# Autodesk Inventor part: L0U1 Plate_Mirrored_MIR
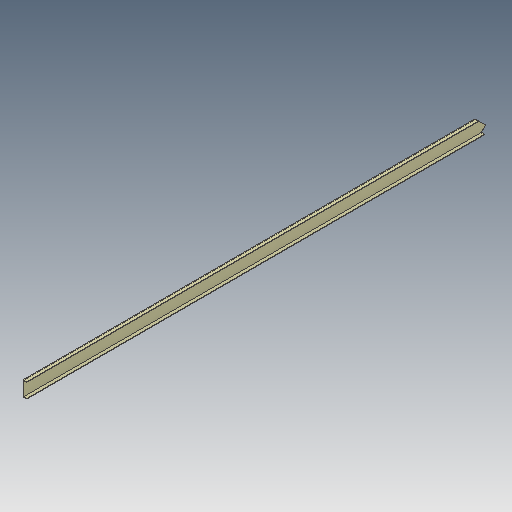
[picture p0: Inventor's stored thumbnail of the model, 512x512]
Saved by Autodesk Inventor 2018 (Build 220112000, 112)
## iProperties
Created: 2018-02
Part Number: L0U1 Plate_Mirrored_MIR
Material: Steel, Mild
Document SubType Name: Sheet Metal
Designer: STK
Density: 7.85 g/cm^3
Sheet Metal Rule: Default
Appearance: Semi-Polished
Mass: 625157 g
Surface Area: 128515 cm^2
Volume: 79637.8 cm^3
Author: STK
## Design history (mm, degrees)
derived "L0U1 Plate_Mirrored.ipt"
feature "Solid1::L0U1 Plate_Mirrored.ipt" dims "d0" = 10
tag "TaggingFeature1"
body "Solid1"
other parameters: "Thickness" = 3.048, "BendRadius" = 3.048 (= Thickness), "BendReliefWidth" = 3.048 (= Thickness), "BendReliefDepth" = 1.524 (= 0.5 x Thickness), "CornerReliefSize" = 12.192 (= 4 x Thickness), "SeamGap" = 0.00508, "MinimumRemnant" = 6.096 (= 2 x Thickness), "TransitionRadius" = 3.048 (= BendRadius), "JacobiRadiusSize" = 3.048 (= BendRadius), "GapSize" = 3.048 (= Thickness)
